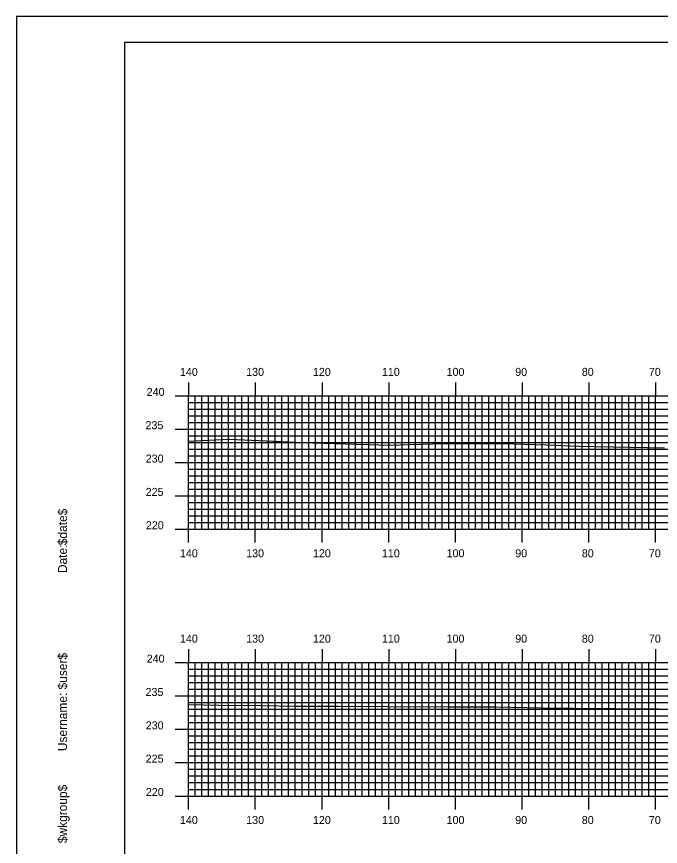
# Model space of a CAD drawing. Extents: x 1803110 to 1803453, y 442591 to 442811.
# Drawn here: x 1803109.8 to 1803206.4, y 442686.1 to 442810.5 of the extents above; entities that cross this region are included whole.
import ezdxf

# ---------------------------------------------------------------- set-up
doc = ezdxf.new("R2010")
doc.units = 0
for name, color, linetype in [('BORDER', 7, 'Continuous'), ('H_V ANNOTATION', 7, 'Continuous'), ('MAJOR', 7, 'Continuous'), ('MINOR', 7, 'Continuous'), ('PLOT BOUNDARY', 7, 'Continuous'), ('S_Roadway_Centerline', 7, 'Continuous')]:
    doc.layers.add(name, color=color, linetype=linetype)

msp = doc.modelspace()

# ---------------------------------------------------------------- linework, layer by layer
at = {"layer": 'BORDER'}
msp.add_lwpolyline([(1803126.03, 442596.67), (1803446.03, 442596.67), (1803446.03, 442806.67), (1803126.03, 442806.67)], close=True, dxfattribs=at)
at = {"layer": 'MAJOR'}
for p, q in [((1803135.63, 442755.67), (1803135.63, 442753.67)), ((1803145.63, 442755.67), (1803145.63, 442753.67)), ((1803155.63, 442755.67), (1803155.63, 442753.67)), ((1803165.63, 442755.67), (1803165.63, 442753.67)), ((1803175.63, 442755.67), (1803175.63, 442753.67)), ((1803185.63, 442755.67), (1803185.63, 442753.67)), ((1803195.63, 442755.67), (1803195.63, 442753.67)), ((1803205.63, 442755.67), (1803205.63, 442753.67)), ((1803133.62, 442753.67), (1803135.63, 442753.67)), ((1803135.63, 442753.67), (1803415.63, 442753.67)), ((1803135.63, 442733.67), (1803135.63, 442753.67)), ((1803135.63, 442733.67), (1803135.63, 442753.67)), ((1803135.63, 442753.67), (1803415.63, 442753.67)), ((1803145.63, 442733.67), (1803145.63, 442753.67)), ((1803155.63, 442733.67), (1803155.63, 442753.67)), ((1803165.63, 442733.67), (1803165.63, 442753.67)), ((1803175.63, 442733.67), (1803175.63, 442753.67)), ((1803185.63, 442733.67), (1803185.63, 442753.67)), ((1803195.63, 442733.67), (1803195.63, 442753.67)), ((1803205.63, 442733.67), (1803205.63, 442753.67)), ((1803133.62, 442748.67), (1803135.63, 442748.67)), ((1803135.63, 442748.67), (1803415.63, 442748.67)), ((1803133.62, 442743.67), (1803135.63, 442743.67)), ((1803135.63, 442743.67), (1803415.63, 442743.67)), ((1803133.62, 442738.67), (1803135.63, 442738.67)), ((1803135.63, 442738.67), (1803415.63, 442738.67)), ((1803133.62, 442733.67), (1803135.63, 442733.67)), ((1803135.63, 442733.67), (1803415.63, 442733.67)), ((1803135.63, 442733.67), (1803415.63, 442733.67)), ((1803135.63, 442731.66), (1803135.63, 442733.67)), ((1803145.63, 442731.66), (1803145.63, 442733.67)), ((1803155.63, 442731.66), (1803155.63, 442733.67)), ((1803165.63, 442731.66), (1803165.63, 442733.67)), ((1803175.63, 442731.66), (1803175.63, 442733.67)), ((1803185.63, 442731.66), (1803185.63, 442733.67)), ((1803195.63, 442731.66), (1803195.63, 442733.67)), ((1803205.63, 442731.66), (1803205.63, 442733.67)), ((1803135.63, 442715.67), (1803135.63, 442713.67)), ((1803145.63, 442715.67), (1803145.63, 442713.67)), ((1803155.63, 442715.67), (1803155.63, 442713.67)), ((1803165.63, 442715.67), (1803165.63, 442713.67)), ((1803175.63, 442715.67), (1803175.63, 442713.67)), ((1803185.63, 442715.67), (1803185.63, 442713.67)), ((1803195.63, 442715.67), (1803195.63, 442713.67)), ((1803205.63, 442715.67), (1803205.63, 442713.67)), ((1803133.62, 442713.67), (1803135.63, 442713.67)), ((1803135.63, 442713.67), (1803415.63, 442713.67)), ((1803135.63, 442693.67), (1803135.63, 442713.67)), ((1803135.63, 442693.67), (1803135.63, 442713.67)), ((1803135.63, 442713.67), (1803415.63, 442713.67)), ((1803145.63, 442693.67), (1803145.63, 442713.67)), ((1803155.63, 442693.67), (1803155.63, 442713.67)), ((1803165.63, 442693.67), (1803165.63, 442713.67)), ((1803175.63, 442693.67), (1803175.63, 442713.67)), ((1803185.63, 442693.67), (1803185.63, 442713.67)), ((1803195.63, 442693.67), (1803195.63, 442713.67)), ((1803205.63, 442693.67), (1803205.63, 442713.67)), ((1803133.62, 442708.67), (1803135.63, 442708.67)), ((1803135.63, 442708.67), (1803415.63, 442708.67)), ((1803133.62, 442703.67), (1803135.63, 442703.67)), ((1803135.63, 442703.67), (1803415.63, 442703.67)), ((1803133.62, 442698.67), (1803135.63, 442698.67)), ((1803135.63, 442698.67), (1803415.63, 442698.67)), ((1803133.62, 442693.67), (1803135.63, 442693.67)), ((1803135.63, 442693.67), (1803415.63, 442693.67)), ((1803135.63, 442693.67), (1803415.63, 442693.67)), ((1803135.63, 442691.66), (1803135.63, 442693.67)), ((1803145.63, 442691.66), (1803145.63, 442693.67)), ((1803155.63, 442691.66), (1803155.63, 442693.67)), ((1803165.63, 442691.66), (1803165.63, 442693.67)), ((1803175.63, 442691.66), (1803175.63, 442693.67)), ((1803185.63, 442691.66), (1803185.63, 442693.67)), ((1803195.63, 442691.66), (1803195.63, 442693.67)), ((1803205.63, 442691.66), (1803205.63, 442693.67))]:
    msp.add_line(p, q, dxfattribs=at)
at = {"layer": 'MINOR'}
for p, q in [((1803135.63, 442752.67), (1803415.63, 442752.67)), ((1803135.63, 442752.67), (1803137.63, 442752.67)), ((1803136.63, 442733.67), (1803136.63, 442753.67)), ((1803137.63, 442733.67), (1803137.63, 442753.67)), ((1803138.63, 442733.67), (1803138.63, 442753.67)), ((1803139.63, 442733.67), (1803139.63, 442753.67)), ((1803140.63, 442733.67), (1803140.63, 442753.67)), ((1803141.63, 442733.67), (1803141.63, 442753.67)), ((1803142.63, 442733.67), (1803142.63, 442753.67)), ((1803143.63, 442733.67), (1803143.63, 442753.67)), ((1803144.63, 442733.67), (1803144.63, 442753.67)), ((1803146.63, 442733.67), (1803146.63, 442753.67)), ((1803147.63, 442733.67), (1803147.63, 442753.67)), ((1803148.63, 442733.67), (1803148.63, 442753.67)), ((1803149.63, 442733.67), (1803149.63, 442753.67)), ((1803150.63, 442733.67), (1803150.63, 442753.67)), ((1803151.63, 442733.67), (1803151.63, 442753.67)), ((1803152.63, 442733.67), (1803152.63, 442753.67)), ((1803153.63, 442733.67), (1803153.63, 442753.67)), ((1803154.63, 442733.67), (1803154.63, 442753.67)), ((1803156.63, 442733.67), (1803156.63, 442753.67)), ((1803157.63, 442733.67), (1803157.63, 442753.67)), ((1803158.63, 442733.67), (1803158.63, 442753.67)), ((1803159.63, 442733.67), (1803159.63, 442753.67)), ((1803160.63, 442733.67), (1803160.63, 442753.67)), ((1803161.63, 442733.67), (1803161.63, 442753.67)), ((1803162.63, 442733.67), (1803162.63, 442753.67)), ((1803163.63, 442733.67), (1803163.63, 442753.67)), ((1803164.63, 442733.67), (1803164.63, 442753.67)), ((1803166.63, 442733.67), (1803166.63, 442753.67)), ((1803167.63, 442733.67), (1803167.63, 442753.67)), ((1803168.63, 442733.67), (1803168.63, 442753.67)), ((1803169.63, 442733.67), (1803169.63, 442753.67)), ((1803170.63, 442733.67), (1803170.63, 442753.67)), ((1803171.63, 442733.67), (1803171.63, 442753.67)), ((1803172.63, 442733.67), (1803172.63, 442753.67)), ((1803173.63, 442733.67), (1803173.63, 442753.67)), ((1803174.63, 442733.67), (1803174.63, 442753.67)), ((1803176.63, 442733.67), (1803176.63, 442753.67)), ((1803177.63, 442733.67), (1803177.63, 442753.67)), ((1803178.63, 442733.67), (1803178.63, 442753.67)), ((1803179.63, 442733.67), (1803179.63, 442753.67)), ((1803180.63, 442733.67), (1803180.63, 442753.67)), ((1803181.63, 442733.67), (1803181.63, 442753.67)), ((1803182.63, 442733.67), (1803182.63, 442753.67)), ((1803183.63, 442733.67), (1803183.63, 442753.67)), ((1803184.63, 442733.67), (1803184.63, 442753.67)), ((1803186.63, 442733.67), (1803186.63, 442753.67)), ((1803187.63, 442733.67), (1803187.63, 442753.67)), ((1803188.63, 442733.67), (1803188.63, 442753.67)), ((1803189.63, 442733.67), (1803189.63, 442753.67)), ((1803190.63, 442733.67), (1803190.63, 442753.67)), ((1803191.63, 442733.67), (1803191.63, 442753.67)), ((1803192.63, 442733.67), (1803192.63, 442753.67)), ((1803193.63, 442733.67), (1803193.63, 442753.67)), ((1803194.63, 442733.67), (1803194.63, 442753.67)), ((1803196.63, 442733.67), (1803196.63, 442753.67)), ((1803197.63, 442733.67), (1803197.63, 442753.67)), ((1803198.63, 442733.67), (1803198.63, 442753.67)), ((1803199.63, 442733.67), (1803199.63, 442753.67)), ((1803200.63, 442733.67), (1803200.63, 442753.67)), ((1803201.63, 442733.67), (1803201.63, 442753.67)), ((1803202.63, 442733.67), (1803202.63, 442753.67)), ((1803203.63, 442733.67), (1803203.63, 442753.67)), ((1803204.63, 442733.67), (1803204.63, 442753.67)), ((1803135.63, 442751.67), (1803415.63, 442751.67)), ((1803135.63, 442751.67), (1803137.63, 442751.67)), ((1803135.63, 442750.67), (1803415.63, 442750.67)), ((1803135.63, 442750.67), (1803137.63, 442750.67)), ((1803135.63, 442749.67), (1803415.63, 442749.67)), ((1803135.63, 442749.67), (1803137.63, 442749.67)), ((1803135.63, 442747.67), (1803415.63, 442747.67)), ((1803135.63, 442747.67), (1803137.63, 442747.67)), ((1803135.63, 442746.67), (1803415.63, 442746.67)), ((1803135.63, 442746.67), (1803137.63, 442746.67)), ((1803135.63, 442745.67), (1803415.63, 442745.67)), ((1803135.63, 442745.67), (1803137.63, 442745.67)), ((1803135.63, 442744.67), (1803415.63, 442744.67)), ((1803135.63, 442744.67), (1803137.63, 442744.67)), ((1803135.63, 442742.67), (1803415.63, 442742.67)), ((1803135.63, 442742.67), (1803137.63, 442742.67)), ((1803135.63, 442741.67), (1803415.63, 442741.67)), ((1803135.63, 442741.67), (1803137.63, 442741.67)), ((1803135.63, 442740.67), (1803415.63, 442740.67)), ((1803135.63, 442740.67), (1803137.63, 442740.67)), ((1803135.63, 442739.67), (1803415.63, 442739.67)), ((1803135.63, 442739.67), (1803137.63, 442739.67)), ((1803135.63, 442737.67), (1803415.63, 442737.67)), ((1803135.63, 442737.67), (1803137.63, 442737.67)), ((1803135.63, 442736.67), (1803415.63, 442736.67)), ((1803135.63, 442736.67), (1803137.63, 442736.67)), ((1803135.63, 442735.67), (1803415.63, 442735.67)), ((1803135.63, 442735.67), (1803137.63, 442735.67)), ((1803135.63, 442734.67), (1803415.63, 442734.67)), ((1803135.63, 442734.67), (1803137.63, 442734.67)), ((1803136.63, 442693.67), (1803136.63, 442713.67)), ((1803137.63, 442693.67), (1803137.63, 442713.67)), ((1803138.63, 442693.67), (1803138.63, 442713.67)), ((1803139.63, 442693.67), (1803139.63, 442713.67)), ((1803140.63, 442693.67), (1803140.63, 442713.67)), ((1803141.63, 442693.67), (1803141.63, 442713.67)), ((1803142.63, 442693.67), (1803142.63, 442713.67)), ((1803143.63, 442693.67), (1803143.63, 442713.67)), ((1803144.63, 442693.67), (1803144.63, 442713.67)), ((1803146.63, 442693.67), (1803146.63, 442713.67)), ((1803147.63, 442693.67), (1803147.63, 442713.67)), ((1803148.63, 442693.67), (1803148.63, 442713.67)), ((1803149.63, 442693.67), (1803149.63, 442713.67)), ((1803150.63, 442693.67), (1803150.63, 442713.67)), ((1803151.63, 442693.67), (1803151.63, 442713.67)), ((1803152.63, 442693.67), (1803152.63, 442713.67)), ((1803153.63, 442693.67), (1803153.63, 442713.67)), ((1803154.63, 442693.67), (1803154.63, 442713.67)), ((1803156.63, 442693.67), (1803156.63, 442713.67)), ((1803157.63, 442693.67), (1803157.63, 442713.67)), ((1803158.63, 442693.67), (1803158.63, 442713.67)), ((1803159.63, 442693.67), (1803159.63, 442713.67)), ((1803160.63, 442693.67), (1803160.63, 442713.67)), ((1803161.63, 442693.67), (1803161.63, 442713.67)), ((1803162.63, 442693.67), (1803162.63, 442713.67)), ((1803163.63, 442693.67), (1803163.63, 442713.67)), ((1803164.63, 442693.67), (1803164.63, 442713.67)), ((1803166.63, 442693.67), (1803166.63, 442713.67)), ((1803167.63, 442693.67), (1803167.63, 442713.67)), ((1803168.63, 442693.67), (1803168.63, 442713.67)), ((1803169.63, 442693.67), (1803169.63, 442713.67)), ((1803170.63, 442693.67), (1803170.63, 442713.67)), ((1803171.63, 442693.67), (1803171.63, 442713.67)), ((1803172.63, 442693.67), (1803172.63, 442713.67)), ((1803173.63, 442693.67), (1803173.63, 442713.67)), ((1803174.63, 442693.67), (1803174.63, 442713.67)), ((1803176.63, 442693.67), (1803176.63, 442713.67)), ((1803177.63, 442693.67), (1803177.63, 442713.67)), ((1803178.63, 442693.67), (1803178.63, 442713.67)), ((1803179.63, 442693.67), (1803179.63, 442713.67)), ((1803180.63, 442693.67), (1803180.63, 442713.67)), ((1803181.63, 442693.67), (1803181.63, 442713.67)), ((1803182.63, 442693.67), (1803182.63, 442713.67)), ((1803183.63, 442693.67), (1803183.63, 442713.67)), ((1803184.63, 442693.67), (1803184.63, 442713.67)), ((1803186.63, 442693.67), (1803186.63, 442713.67)), ((1803187.63, 442693.67), (1803187.63, 442713.67)), ((1803188.63, 442693.67), (1803188.63, 442713.67)), ((1803189.63, 442693.67), (1803189.63, 442713.67)), ((1803190.63, 442693.67), (1803190.63, 442713.67)), ((1803191.63, 442693.67), (1803191.63, 442713.67)), ((1803192.63, 442693.67), (1803192.63, 442713.67)), ((1803193.63, 442693.67), (1803193.63, 442713.67)), ((1803194.63, 442693.67), (1803194.63, 442713.67)), ((1803196.63, 442693.67), (1803196.63, 442713.67)), ((1803197.63, 442693.67), (1803197.63, 442713.67)), ((1803198.63, 442693.67), (1803198.63, 442713.67)), ((1803199.63, 442693.67), (1803199.63, 442713.67)), ((1803200.63, 442693.67), (1803200.63, 442713.67)), ((1803201.63, 442693.67), (1803201.63, 442713.67)), ((1803202.63, 442693.67), (1803202.63, 442713.67)), ((1803203.63, 442693.67), (1803203.63, 442713.67)), ((1803204.63, 442693.67), (1803204.63, 442713.67)), ((1803135.63, 442712.67), (1803415.63, 442712.67)), ((1803135.63, 442712.67), (1803137.63, 442712.67)), ((1803135.63, 442711.67), (1803415.63, 442711.67)), ((1803135.63, 442711.67), (1803137.63, 442711.67)), ((1803135.63, 442710.67), (1803415.63, 442710.67)), ((1803135.63, 442710.67), (1803137.63, 442710.67)), ((1803135.63, 442709.67), (1803415.63, 442709.67)), ((1803135.63, 442709.67), (1803137.63, 442709.67)), ((1803135.63, 442707.67), (1803415.63, 442707.67)), ((1803135.63, 442707.67), (1803137.63, 442707.67)), ((1803135.63, 442706.67), (1803415.63, 442706.67)), ((1803135.63, 442706.67), (1803137.63, 442706.67)), ((1803135.63, 442705.67), (1803415.63, 442705.67)), ((1803135.63, 442705.67), (1803137.63, 442705.67)), ((1803135.63, 442704.67), (1803415.63, 442704.67)), ((1803135.63, 442704.67), (1803137.63, 442704.67)), ((1803135.63, 442702.67), (1803415.63, 442702.67)), ((1803135.63, 442702.67), (1803137.63, 442702.67)), ((1803135.63, 442701.67), (1803415.63, 442701.67)), ((1803135.63, 442701.67), (1803137.63, 442701.67)), ((1803135.63, 442700.67), (1803415.63, 442700.67)), ((1803135.63, 442700.67), (1803137.63, 442700.67)), ((1803135.63, 442699.67), (1803415.63, 442699.67)), ((1803135.63, 442699.67), (1803137.63, 442699.67)), ((1803135.63, 442697.67), (1803415.63, 442697.67)), ((1803135.63, 442697.67), (1803137.63, 442697.67)), ((1803135.63, 442696.67), (1803415.63, 442696.67)), ((1803135.63, 442696.67), (1803137.63, 442696.67)), ((1803135.63, 442695.67), (1803415.63, 442695.67)), ((1803135.63, 442695.67), (1803137.63, 442695.67)), ((1803135.63, 442694.67), (1803415.63, 442694.67)), ((1803135.63, 442694.67), (1803137.63, 442694.67))]:
    msp.add_line(p, q, dxfattribs=at)
at = {"layer": 'PLOT BOUNDARY'}
msp.add_lwpolyline([(1803109.84, 442590.55), (1803449.84, 442590.55), (1803449.84, 442810.55), (1803109.84, 442810.55)], close=True, dxfattribs=at)
at = {"layer": 'S_Roadway_Centerline'}
for points in [[(1803135.63, 442746.89), (1803141.75, 442747.18), (1803150.56, 442746.76), (1803152.65, 442746.66), (1803155.87, 442746.58), (1803165.77, 442746.27), (1803172.18, 442746.48), (1803176.51, 442746.55), (1803182.73, 442746.51), (1803189.31, 442746.31), (1803194.07, 442746.15), (1803207, 442745.88)], [(1803135.63, 442707.39), (1803140.15, 442707.27), (1803146.59, 442707.25), (1803151.78, 442707.13), (1803158.15, 442707.13), (1803165.41, 442707.11), (1803174.74, 442707.06), (1803181.66, 442707.04), (1803191.16, 442706.82), (1803193.28, 442706.83), (1803212.45, 442706.67)]]:
    msp.add_lwpolyline(points, dxfattribs=at)

# ---------------------------------------------------------------- texts
at = {"layer": 'BORDER'}
for s, p in [('$date$', (1803117.4, 442731.28)), ('Date:', (1803117.4, 442727.1)), ('$user$', (1803117.4, 442709.65)), ('Username:', (1803117.4, 442700.4)), ('$wkgroup$', (1803117.4, 442686.6))]:
    msp.add_text(s, height=1.339, rotation=90, dxfattribs=at).set_placement(p)
at = {"layer": 'H_V ANNOTATION'}
for s, p in [('140', (1803134.33, 442756.67)), ('130', (1803144.26, 442756.67)), ('120', (1803154.27, 442756.67)), ('110', (1803164.61, 442756.67)), ('100', (1803174.31, 442756.67)), ('90', (1803184.6, 442756.67)), ('80', (1803194.58, 442756.67)), ('70', (1803204.63, 442756.67)), ('240', (1803129.35, 442753.67)), ('235', (1803129.17, 442748.67)), ('230', (1803129.2, 442743.67)), ('225', (1803129.19, 442738.67)), ('220', (1803129.22, 442733.67)), ('140', (1803134.33, 442729.47)), ('130', (1803144.26, 442729.47)), ('120', (1803154.27, 442729.47)), ('110', (1803164.61, 442729.47)), ('100', (1803174.31, 442729.47)), ('90', (1803184.6, 442729.47)), ('80', (1803194.58, 442729.47)), ('70', (1803204.63, 442729.47)), ('140', (1803134.33, 442716.67)), ('130', (1803144.26, 442716.67)), ('120', (1803154.27, 442716.67)), ('110', (1803164.61, 442716.67)), ('100', (1803174.31, 442716.67)), ('90', (1803184.6, 442716.67)), ('80', (1803194.58, 442716.67)), ('70', (1803204.63, 442716.67)), ('240', (1803129.35, 442713.67)), ('235', (1803129.17, 442708.67)), ('230', (1803129.2, 442703.67)), ('225', (1803129.19, 442698.67)), ('220', (1803129.22, 442693.67)), ('140', (1803134.33, 442689.47)), ('130', (1803144.26, 442689.47)), ('120', (1803154.27, 442689.47)), ('110', (1803164.61, 442689.47)), ('100', (1803174.31, 442689.47)), ('90', (1803184.6, 442689.47)), ('80', (1803194.58, 442689.47)), ('70', (1803204.63, 442689.47))]:
    msp.add_text(s, height=1.2, dxfattribs=at).set_placement(p)
at = {"layer": 'MAJOR'}
for p in [(1803135.62, 442733.67), (1803135.62, 442693.67)]:
    msp.add_text('-', height=0.012, dxfattribs=at).set_placement(p)

doc.saveas('drawing.dxf')
